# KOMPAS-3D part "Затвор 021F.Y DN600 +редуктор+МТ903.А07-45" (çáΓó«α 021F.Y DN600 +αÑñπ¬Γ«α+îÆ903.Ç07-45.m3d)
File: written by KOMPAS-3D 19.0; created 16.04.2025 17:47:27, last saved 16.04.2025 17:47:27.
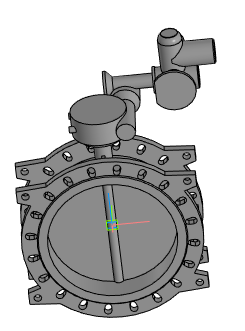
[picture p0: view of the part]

Document properties: Полное имя файла: Затвор 021F.Y DN600 +редуктор+МТ903.А07-45.a3d

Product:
- Part/product: Затвор 021F.Y DN600 +редуктор+МТ903.А07-45
    Масса: 421.2

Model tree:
1. Операция без истории:1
